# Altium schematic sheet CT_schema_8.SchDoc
size 398 x 245 mm
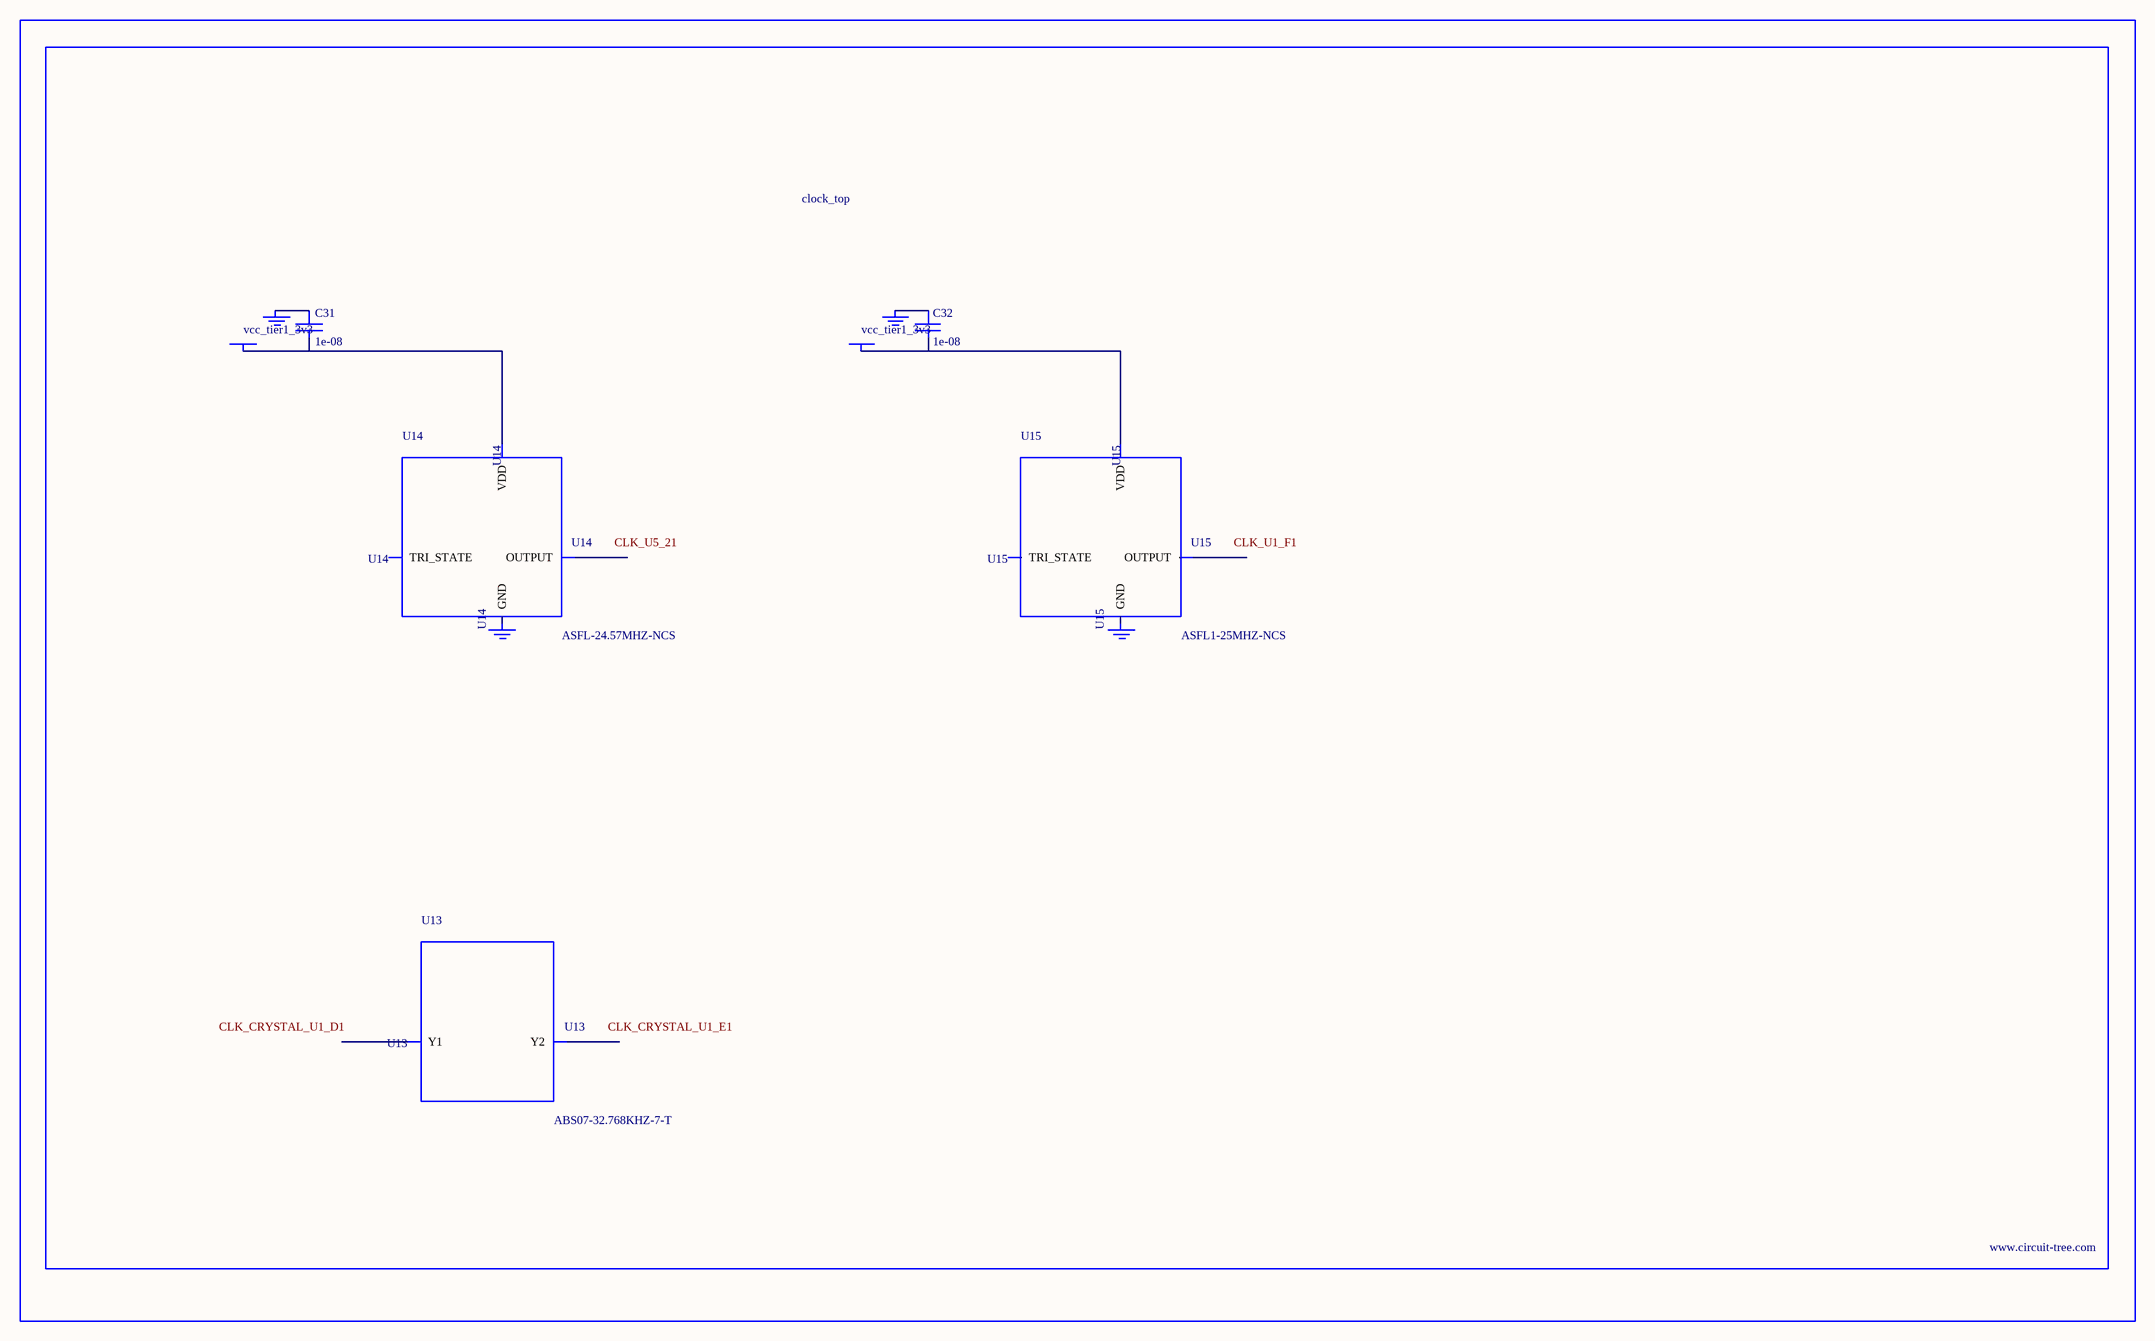
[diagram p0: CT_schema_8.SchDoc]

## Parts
BORDER7  (no value)
C31  1e-08  [C0402]
C32  1e-08  [C0402]
GND_INSTANCE_7_0  (no value)
GND_INSTANCE_7_1  (no value)
GND_INSTANCE_7_2  (no value)
GND_INSTANCE_7_3  (no value)
POWER_INSTANCE_7_0  vcc_tier1_3v3
POWER_INSTANCE_7_1  vcc_tier1_3v3
U13  ABS07-32.768KHZ-7-T  [ABS07-32.768KHZ-7-T]
U14  ASFL-24.57MHZ-NCS  [ASFL1]
U15  ASFL1-25MHZ-NCS  [ASFL1]

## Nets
NetC31_1: C31.1 GND_INSTANCE_7_0.0(GND)
NetC31_2: C31.2 POWER_INSTANCE_7_0.0(PWR) U14.4(VDD)
NetC32_1: C32.1 GND_INSTANCE_7_2.0(GND)
NetC32_2: C32.2 POWER_INSTANCE_7_1.0(PWR) U15.4(VDD)

Not connected (* = marked no-connect by the designer): GND_INSTANCE_7_1 0(GND); GND_INSTANCE_7_3 0(GND); U13 1(Y1) 2(Y2); U14 1(TRI_STATE) 2(GND) 3(OUTPUT); U15 1(TRI_STATE) 2(GND) 3(OUTPUT)

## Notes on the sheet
- Labels drawn without touching a wire or pin: CLK_CRYSTAL_U1_D1, CLK_CRYSTAL_U1_E1, CLK_U1_F1, CLK_U5_21

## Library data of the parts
BORDER7 = BORDER_PAGE7
C31 C32 = C0402C103K3RAC
GND_INSTANCE_7_0-GND_INSTANCE_7_3 = GND
POWER_INSTANCE_7_0 POWER_INSTANCE_7_1 = PWR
